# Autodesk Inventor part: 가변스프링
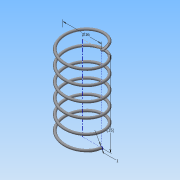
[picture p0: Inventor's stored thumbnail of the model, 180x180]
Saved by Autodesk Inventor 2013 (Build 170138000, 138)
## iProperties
Created: 2016-12
Part Number: 가변스프링
Material: 일반
Document SubType Name: Modeling
Designer: Administrator
Density: 1 g/cm^3
Mass: -0.00167452 g
Surface Area: 9.47151 cm^2
Volume: -0.00167452 cm^3
Author: Administrator
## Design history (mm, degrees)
sketch "스케치1"
  geometry: L1 (0, 0)-(8, 0); L2 (8, 0)-(8, 30.474); L3 (8, 30.474)-(0, 30.474); L4 (0, 30.474)-(0, 0); C1 r 0.5 at (8, 0)
  constraints: 8 end point, 2 parallel, 1 centre point, 1 coincident, 1 horizontal, 1 perpendicular
  dimensions: "d0" = 1 diameter of C1; "d1" = 30.4737 distance of L1.end L2.end (derived); "d2" = 16 diameter of L2 L4
feature "코일1" pitch "d3" = 10; turns "d5" = 6; dims "d4" = 30.4737 (= d1), "d6" = 0, angle "d7" = 90 deg, angle "d8" = 90 deg, "d9" = 0, "d10" = 0
sketch "스케치2"
  geometry: L1 (-7.5, 0)-(-8.5, 0) reference; 1 further point
  constraints: 1 horizontal alignment
extrude "돌출1" cut sketch "스케치2" stored distance "d11" = 10; taper "d12" = 0 deg
node "작업 평면1"
sketch "스케치3"
  geometry: L1 (-0.5, 0)-(0.5, 0) reference; 1 further point
  constraints: 1 horizontal alignment
extrude "돌출2" cut sketch "스케치3" stored distance "d14" = 10; taper "d15" = 0 deg
node "솔리드1"
node "절단 모서리 투영1"
node "절단 모서리 투영2"
other parameters: "d13" = 90 deg
